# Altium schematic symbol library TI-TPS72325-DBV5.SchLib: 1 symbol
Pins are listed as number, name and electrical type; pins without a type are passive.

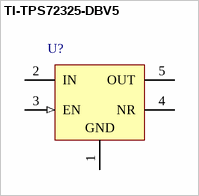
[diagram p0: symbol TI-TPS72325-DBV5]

## TI-TPS72325-DBV5
designator U?
TPS72325 Negative Voltage Regulator
footprint TI-DBV5_N (SOT23, 5-Leads, Body 2.9x1.6mm, Pitch 0.95mm, IPC Medium Density)
pins: 1 GND (power) "Ground", 2 IN (power) "Input supply", 3 EN (in) "Bipolar enable pin. Driving this pin above the positive enable threshold or below the negative enable threshold turns on the regulator. Driving this pin below the positive disable threshold and above the negative disable (See Datasheet)", 4 NR "Fixed-voltage versions only. Connecting an external capacitor between this pin and ground bypasses noise generated by the internal band gap. This configuration allows output noise to be reduced to very low levels.", 5 OUT (power) "Regulated output voltage. The device requires the connection of a small 2.2-uF ceramic capacitor from this pin to GND to ensure stability."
